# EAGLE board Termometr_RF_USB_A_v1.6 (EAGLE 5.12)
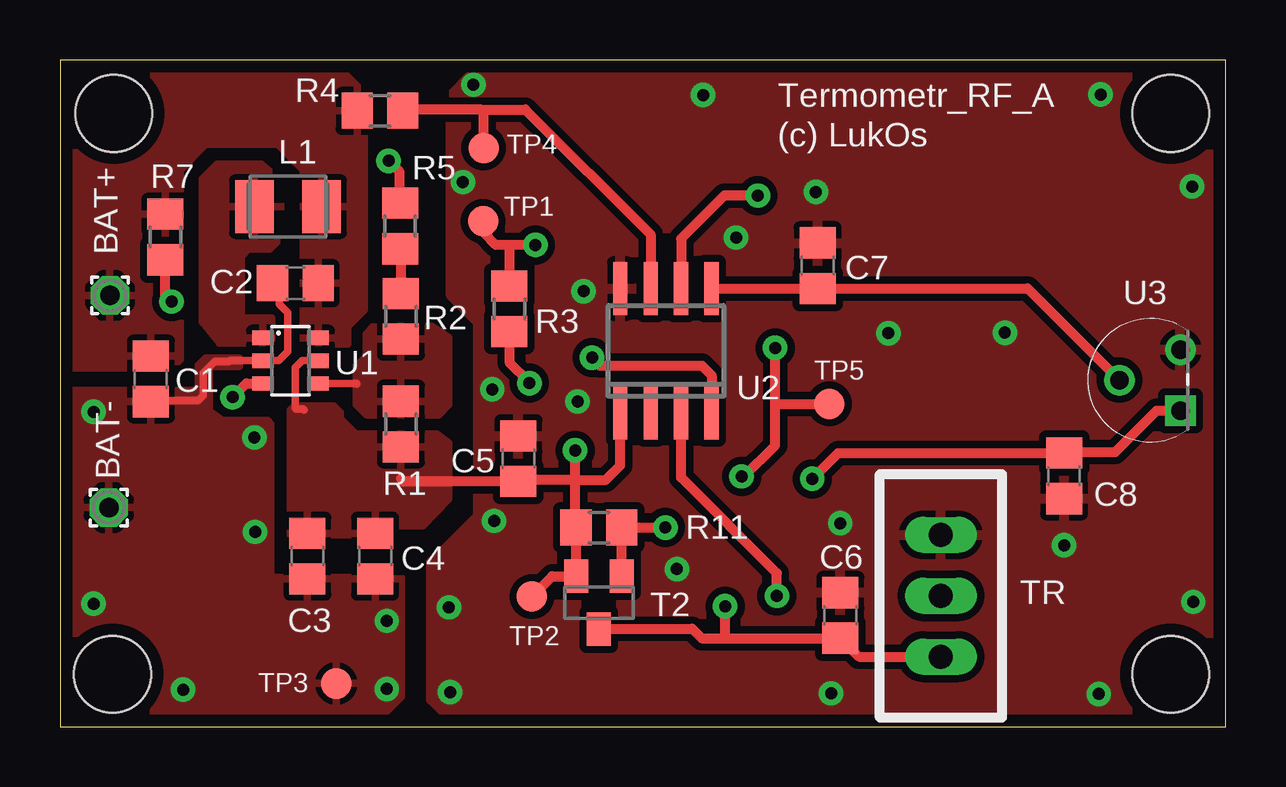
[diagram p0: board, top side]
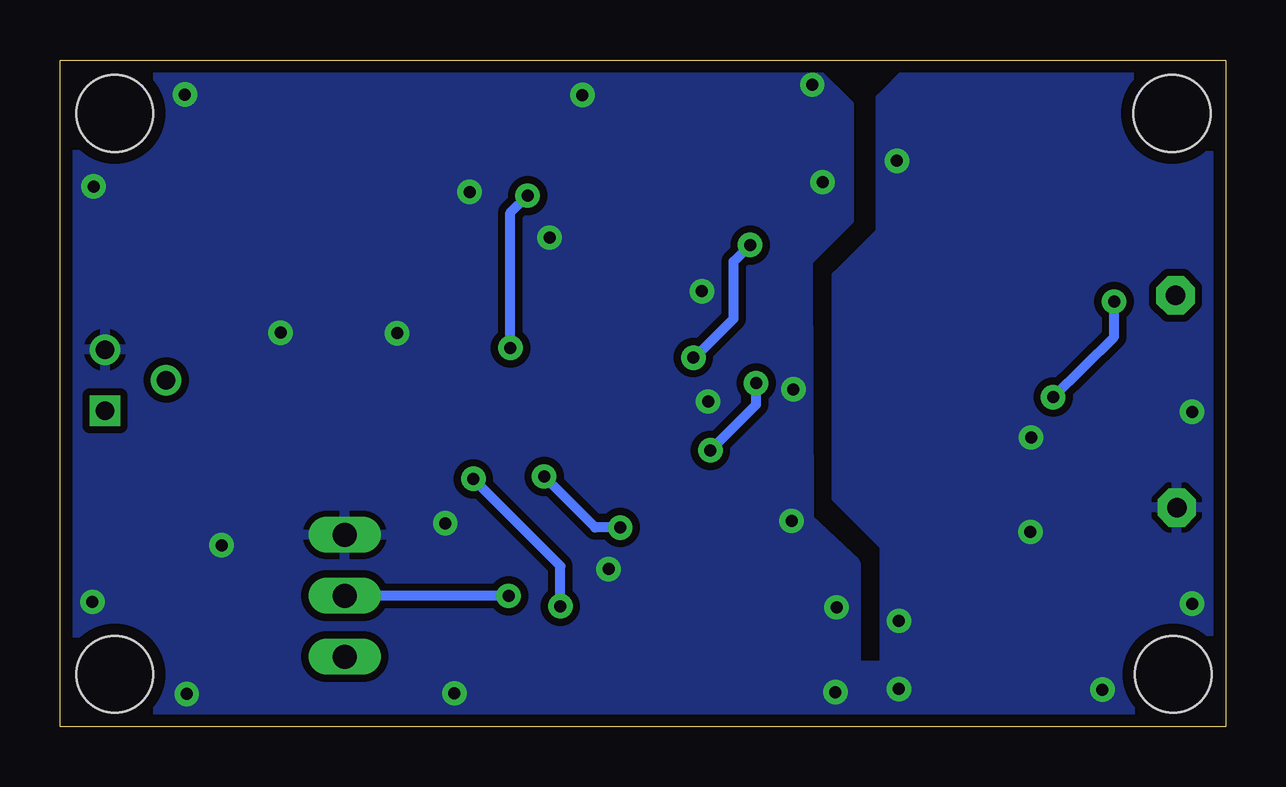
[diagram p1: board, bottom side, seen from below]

Size 48.56 x 27.8 mm. Coordinates in mm from the lower left corner, seen from the top.
Outline: 0,0 48.56,0 48.56,27.8 0,27.8 0,0
Copper layers (1*16): Top 0.035mm / dielectric 1.5mm / Bottom 0.035mm
Design rules "default *": minimum track width 10mil, minimum drill 19mil, track to track 8mil, track to pad 8mil, pad to pad 8mil, via to via 8mil, smd to smd 8mil, copper to edge 20mil, drill to drill 8mil, minimum pad ring 10mil, minimum via ring 8mil, stop-mask expansion 4mil, vias tented up to drill 0mil, thermal gap 10mil
Holes 3.2 mm at 2.24,25.58 2.18,2.18 46.28,2.18 46.28,25.58

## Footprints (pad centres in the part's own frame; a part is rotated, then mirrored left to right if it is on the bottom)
1,6/0,8 = drill 0.813 pad 1.6 octagon: 1 0,0
C0805 = smd 1.3 x 1.5: 1 -0.95,0; 2 0.95,0
L3230M = smd 1.6 x 2.2: 1 -1.4,0; 2 1.4,0
R0805 = smd 1.3 x 1.5: 1 -0.95,0; 2 0.95,0
SOT23 = smd 1 x 1.4: 1 -0.95,-1.1; 2 0.95,-1.1; 3 0,1.1
B1,27 = smd 1.27 x 1.27: TP 0,0
3PIN = drill 1 long: GND 2.54,0; IN 0,0; VDD -2.54,0
SOT23-6 = smd 0.6 x 0.9: 1 -0.95,-1.15; 2 0,-1.15; 3 0.95,-1.15; 4 0.95,1.15; 5 0,1.15; 6 -0.95,1.15
SO-08 = smd 0.6 x 2.2: 1 -1.905,-2.6; 2 -0.635,-2.6; 3 0.635,-2.6; 4 1.905,-2.6; 5 1.905,2.6; 6 0.635,2.6; 7 -0.635,2.6; 8 -1.905,2.6
TO127P254X533-3P = drill 0.762 square: 1 -2.54,-2.54 | drill 0.762 round: 2 -1.27,0; 3 0,-2.54

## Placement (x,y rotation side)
BAT+  WIREPAD1,6/0,8  [1,6/0,8]  2.08,17.98 0 top
BAT-  WIREPAD1,6/0,8  [1,6/0,8]  2.03,9.14 0 top
C1  100n  [C0805]  3.78,14.5 270 top
C2  22uF  [C0805]  9.8,18.49 0 top
C3  22uF  [C0805]  10.31,7.11 90 top
C4  100n  [C0805]  13.13,7.11 90 top
C5  100n  [C0805]  19.1,11.18 90 top
C6  100n  [C0805]  32.51,4.65 90 top
C7  10n  [C0805]  31.57,19.23 90 top
C8  100n  [C0805]  41.83,10.46 270 top
L1  4.7uH  [L3230M]  9.5,21.69 180 top
R1  6.98M  [R0805]  14.2,12.62 270 top
R2  2.0M  [R0805]  14.2,17.12 270 top
R3  100k  [R0805]  18.72,17.42 270 top
R4  4.7k  [R0805]  13.34,25.68 0 top
R5  2.0M  [R0805]  14.17,20.88 270 top
R7  1M  [R0805]  4.39,20.42 90 top
R11  1M  [R0805]  22.45,8.31 180 top
T2  BSS84  [SOT23]  22.45,5.18 180 top
TP1  PTR1B1,27  [B1,27]  17.63,21.08 0 top
TP2  PTR1B1,27  [B1,27]  19.66,5.44 0 top
TP3  PTR1B1,27  [B1,27]  11.51,1.8 0 top
TP4  PTR1B1,27  [B1,27]  17.65,24.13 0 top
TP5  PTR1B1,27  [B1,27]  32.05,13.46 0 top
TR  HM-T868  [3PIN]  36.7,5.46 90 top
U1  MCP1640  [SOT23-6]  9.6,15.27 270 top
U2  PIC12F1822SN  [SO-08]  25.25,15.67 0 top
U3  TMP36GT9Z  [TO127P254X533-3P]  44.15,15.72 90 top

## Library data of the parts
BAT+ BAT- C1-C8 L1 R1-R5 R7 R11 = Luk_lib
T2 = transistor-small-signal
TP1-TP5 = testpad
TR = hope_rf
U1 = MCP1640
U2 = pic12f1822
U3 = TMP36; MPN: TMP36GT9Z; OC_FARNELL: 1438760; OC_NEWARK: 19M9015; PACKAGE: TO-92; SUPPLIER: Analog Devices

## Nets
!MCLR: R3.1 TP1.TP U2.4
+3V3: C3.2 C4.2 C5.1 R1.2 R3.2 R11.2 T2.2 TP2.TP U1.5 U2.1
+3V3_SW: C6.1 C8.1 T2.3 TR.VDD U3.1
BAT+: BAT+.1 C1.1 C2.2 L1.1 R4.1 R7.2 U1.6
GND: BAT-.1 C1.2 C2.1 C3.1 C4.1 C5.2 C6.2 C7.2 C8.2 R5.1 TP3.TP TR.GND U1.2 U2.8 U3.3
ICSPCLK: R11.1 T2.1 TP5.TP U2.6
ICSPDAT: R4.2 TP4.TP U2.7
N$1: C7.1 U2.5 U3.2
N$2: R1.1 R2.2 U1.4
N$3: L1.2 U1.1
N$4: R7.1 U1.3
N$6: R2.1 R5.2
TX: TR.IN U2.3

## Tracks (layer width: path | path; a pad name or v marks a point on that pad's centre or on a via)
!MCLR  (via drill 0.5 pad 1.02)
  Top 0.406: U2.4 27.15,14.66 26.75,15.06 22.5,15.06 v22.17,15.39 | 18.59,20.09 18.16,20.09 17.68,20.57 17.68,21.03 TP1.TP | v19.81,20.09 18.59,20.09 | R3.1 18.72,19.96 18.59,20.09
  Bottom 0.406: v22.17,15.39 22.12,15.39 20.5,17.02 20.5,19.41 v19.81,20.09
+3V3  (via drill 0.5 pad 1.02)
  Top 0.305: 10.19,13.21 10.13,13.26 9.83,13.26 9.8,13.28 9.8,14.99 10.08,15.27 U1.5
  Top 0.406: 14.2,10.34 14.31,10.23 C5.1 19.18,10.3 21.46,10.3 | 21.46,10.3 22.75,10.3 23.34,10.9 U2.1 | 21.46,10.3 v21.46,11.53 | 21.46,10.3 21.46,8.35 R11.2 T2.2 20.51,6.28 TP2.TP | v19.56,14.33 19.54,14.34 19.54,14.37 18.75,15.16 18.75,16.45 R3.2
  Bottom 0.406: v19.56,14.33 19.56,13.44 v21.46,11.53
  pour Top (isolate 0.305): 9.6,13.21 9.6,8 13.16,8 13.79,8.38 15.11,8.38 16.21,9.5 16.21,11.84 15.7,12.22 12.32,12.22 11.68,12.85 11.68,13.11 11.4,13.39 9.78,13.39
+3V3_SW  (via drill 0.5 pad 1.02)
  Top 0.406: TR.VDD 33.29,2.92 C6.1 27.61,3.7 | 27.61,3.7 26.73,3.7 26.34,4.09 T2.3 | v27.71,5.03 27.71,3.8 27.61,3.7 | v31.34,10.34 32.42,11.41 C8.1 41.87,11.46 43.97,11.46 45.7,13.18 U3.1
  Bottom 0.406: v27.71,5.03 27.71,6.71 v31.34,10.34
BAT+
  pour Top (isolate 0.305): 11.07,15.95 11.99,15.95 11.99,16.69 12.67,17.37 12.67,26.42 11.66,27.43 0.43,27.43 0.41,23.93 0.38,14.96 4.65,14.96 5,15.32 5,23.22 6.07,24.28 9.07,24.28 10.13,23.22 10.13,16.03 10.16,16 10.16,15.95 10.13,15.93
GND  (via drill 0.5 pad 1.02)
  Top 0.305: 9.17,18.28 C2.1 9.14,18.2 9.14,17.63 9.5,17.27 9.5,15.65 9.12,15.27 U1.2 7.09,15.27 7.06,15.24 6.45,15.24 5.97,14.76 5.97,13.82 5.77,13.61 3.85,13.61 C1.2
  Top 0.406: R5.1 14.15,21.83 14.15,23.14 v13.69,23.6
  Bottom 0.406: v13.69,23.6 13.51,23.6 13.49,23.62
  other vias: 21.56,13.56 1.4,5.13 1.4,13.13 13.61,1.57 43.36,26.37 47.17,22.53 47.22,5.21 43.28,1.37 16.26,1.45 16.21,4.98 26.8,26.34 21.82,18.16 32.51,8.48 32.13,1.4 41.83,7.57 8.13,8.13 13.61,4.42 25.7,6.58 18.08,8.59 18.01,14.07 34.52,16.41 28.17,20.4 39.37,16.43 31.5,22.3 17.22,26.77 5.13,1.55 8.1,12.06 16.79,22.71
  pour Top (isolate 0.305): 0.23,14.02 5.77,14.05 5.77,15.06 6.07,15.37 7.47,15.37 7.47,15.01 6.4,15.01 6.22,14.99 6.22,13.16 6.76,12.78 8.66,12.78 8.79,12.62 8.79,6.22 14.22,6.22 14.22,1.24 13.21,0.23 0.25,0.23
  pour Top (isolate 0.305): 15.47,1.12 15.47,6.86 17.42,8.81 17.42,16.84 16.28,17.98 16.28,26.34 17.14,27.2 48.06,27.2 48.06,0.61 16,0.58
  pour Bottom (isolate 0.305): 0.53,27.46 0.53,0.53 47.88,0.53 47.93,0.48 47.93,27.28 17.04,27.28 15.7,25.96 15.7,21.11 17.4,19.41 17.37,8.66 15.42,6.83 15.42,2.57 14.2,2.57 14.2,7.52 16.21,9.53 16.21,18.82 14.38,20.65 14.38,26.21 13.16,27.43 0.56,27.43
ICSPCLK  (via drill 0.5 pad 1.02)
  Top 0.406: T2.1 R11.1 v25.22,8.31 | U2.6 25.88,20.34 27.69,22.15 v29.08,22.15 | 29.79,13.41 29.79,11.73 28.5,10.44 v28.4,10.44 | 29.79,13.41 v29.79,15.8 | TP5.TP 29.84,13.46 29.79,13.41
  Bottom 0.406: v25.22,8.31 26.26,8.31 v28.4,10.44 | v29.79,15.8 29.79,21.44 v29.08,22.15
ICSPDAT
  Top 0.406: R4.2 14.29,25.74 17.53,25.74 | 17.53,25.74 19.39,25.74 24.61,20.52 U2.7 | TP4.TP 17.65,25.61 17.53,25.74
N$1
  Top 0.406: U2.5 C7.1 40.32,18.28 U3.2
N$2
  Top 0.305: U1.4 12.36,14.31 12.37,14.3
  pour Top (isolate 0.305): 15.52,16.69 13.06,16.69 12.75,16.38 12.75,15.44 12.34,15.04 12.34,13.44 12.78,13 15.77,13 16.21,13.44 16.21,16.23
N$3
  pour Top (isolate 0.305): 8.38,23.47 6.55,23.47 5.92,22.83 5.92,16.87 6.63,16 8.71,16 8.81,16.1 8.81,17.04 7.54,17.04 7.54,19.61 7.85,19.91 8.74,19.91 9.19,20.37 9.19,22.81
N$4  (via drill 0.5 pad 1.02)
  Top 0.406: R7.1 4.39,17.98 v4.65,17.73 | U1.3 7.76,14.31 v7.19,13.74
  Bottom 0.406: v4.65,17.73 4.65,16.26 v7.19,13.74
N$6
  Top 0.406: R2.1 14.2,19.9 R5.2
TX  (via drill 0.5 pad 1.02)
  Top 0.406: U2.3 25.88,10.39 29.87,6.4 v29.87,5.46
  Bottom 0.406: v29.87,5.46 TR.IN

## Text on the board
tNames: Termometr_RF_A | (c) LukOs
